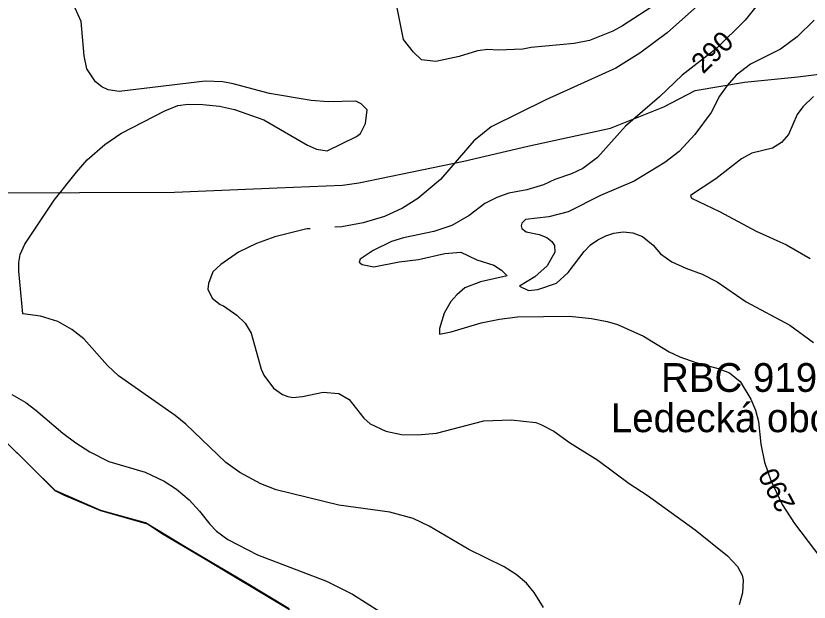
# Model space of a CAD drawing. Extents: x -662620 to -656370, y -1067090 to -1062990.
# Drawn here: x -662202 to -661678, y -1066558 to -1066171 of the extents above; entities that cross this region are included whole.
import ezdxf

# ---------------------------------------------------------------- set-up
doc = ezdxf.new("R2010")
doc.units = 0
for name, color, linetype in [('HRANICE_KATASTRÁLNÍHO_ÚZEMÍ', 7, 'Continuous'), ('Popis_-_Regionální_biocentrum_-_stávající', 7, 'Continuous'), ('Regionální_biocentrum_-_stávající', 7, 'Continuous'), ('VRSTEVNICE_ZDŮRAZNĚNÁ', 7, 'Continuous'), ('VRSTEVNICE_ZDŮRAZNĚNÁ_-_POPIS', 7, 'Continuous'), ('VRSTEVNICE_ZÁKLADNÍ', 7, 'Continuous')]:
    doc.layers.add(name, color=color, linetype=linetype)

msp = doc.modelspace()

# ---------------------------------------------------------------- linework, layer by layer
at = {"layer": 'HRANICE_KATASTRÁLNÍHO_ÚZEMÍ'}
msp.add_lwpolyline([(-662021.74, -1066563.07), (-662078.28, -1066529.15), (-662106.1, -1066512.72), (-662115.48, -1066506.62), (-662146.3, -1066497.76), (-662170.31, -1066487.67), (-662176.36, -1066484.43), (-662192.31, -1066468.76), (-662209.65, -1066451.51)], dxfattribs=at)
at = {"layer": 'Regionální_biocentrum_-_stávající'}
for points in [[(-662215.01, -1066287.86), (-662160.39, -1066287.51), (-662097.67, -1066287.27), (-662029.78, -1066284.52), (-661986.68, -1066282.77), (-661975.88, -1066281.2), (-661906.57, -1066266.8), (-661864.31, -1066256.88), (-661809.67, -1066245.03), (-661774.44, -1066231.02), (-661753.74, -1066220.18), (-661721.21, -1066214.63), (-661685.97, -1066211.19), (-661666.49, -1066208.88)], [(-662021.93, -1066562.42), (-662051.78, -1066544.4), (-662089.89, -1066522.03), (-662116.77, -1066505.74), (-662146.27, -1066497.59), (-662176.53, -1066484.26), (-662210.25, -1066450.85)]]:
    msp.add_lwpolyline(points, dxfattribs=at)
at = {"layer": 'VRSTEVNICE_ZDŮRAZNĚNÁ'}
for points in [[(-661709.26, -1066159.19), (-661720.68, -1066173.89), (-661739.66, -1066192.45), (-661762.21, -1066210.15), (-661777.2, -1066224.42), (-661799.75, -1066243.84), (-661818.31, -1066264.39), (-661827.87, -1066271.67), (-661835.3, -1066275.24), (-661846.43, -1066278.95), (-661853.85, -1066282.52), (-661864.98, -1066285.8), (-661876.69, -1066288.08), (-661884.68, -1066290.8), (-661892.68, -1066294.94), (-661902.95, -1066302.79), (-661914.37, -1066309.35), (-661926.36, -1066313.35), (-661946.35, -1066317.49), (-661954.34, -1066319.92), (-661966.33, -1066325.91), (-661975.04, -1066331.62), (-661975.61, -1066333.62), (-661973.75, -1066335.05), (-661966.04, -1066336.76), (-661949.2, -1066333.33), (-661936.35, -1066331.91), (-661918.94, -1066327.77), (-661908.38, -1066327.05), (-661897.82, -1066332.05)], [(-661897.82, -1066332.05), (-661886.68, -1066335.62), (-661881.69, -1066338.76), (-661877.87, -1066342.56), (-661895.53, -1066346.46), (-661905.81, -1066350.6), (-661911.09, -1066355.03), (-661915.09, -1066359.45), (-661919.51, -1066367.16), (-661922.51, -1066377.44), (-661922.51, -1066381.15), (-661914.94, -1066379.58), (-661894.96, -1066373.58), (-661882.97, -1066371.16), (-661870.98, -1066369.59), (-661836.72, -1066369.3), (-661822.16, -1066370.87), (-661811.89, -1066372.73), (-661805.04, -1066374.73), (-661787.91, -1066382.43), (-661770.78, -1066392.71), (-661763.93, -1066396.14), (-661753.36, -1066399.85), (-661738.52, -1066403.85), (-661731.1, -1066406.7), (-661723.96, -1066412.27), (-661716.97, -1066423.97), (-661713.83, -1066431.39), (-661711.97, -1066438.82), (-661710.26, -1066453.66), (-661707.83, -1066465.65), (-661703.69, -1066477.64), (-661696.27, -1066493.63), (-661688.13, -1066506.19), (-661657.44, -1066546.3)]]:
    msp.add_lwpolyline(points, dxfattribs=at)
at = {"layer": 'VRSTEVNICE_ZÁKLADNÍ'}
for points in [[(-661778.63, -1066162.47), (-661801.61, -1066177.61), (-661808.18, -1066181.17), (-661823.59, -1066187.31), (-661833.58, -1066189.31), (-661862.13, -1066191.74), (-661867.55, -1066192.88), (-661883.83, -1066193.59), (-661890.68, -1066193.16), (-661897.53, -1066194.02), (-661909.52, -1066197.73), (-661924.93, -1066201.01), (-661934.5, -1066200.02), (-661939.64, -1066194.88), (-661946.34, -1066186.6), (-661951.48, -1066161.19)], [(-661778.63, -1066162.47), (-661801.61, -1066177.61), (-661808.18, -1066181.17), (-661823.59, -1066187.31), (-661833.58, -1066189.31), (-661862.13, -1066191.74), (-661867.55, -1066192.88), (-661883.83, -1066193.59), (-661890.68, -1066193.16), (-661897.53, -1066194.02), (-661909.52, -1066197.73), (-661924.93, -1066201.01), (-661934.5, -1066200.02), (-661939.64, -1066194.88), (-661946.34, -1066186.6), (-661951.48, -1066161.19)], [(-662009.86, -1066256.4), (-662003.73, -1066258.97), (-661996.88, -1066259.97), (-661977.46, -1066250.69), (-661974.75, -1066248.69), (-661971.47, -1066242.12), (-661970.36, -1066232.9), (-661974.35, -1066229.11), (-661977.94, -1066227.17), (-661996.02, -1066227.71), (-662007.44, -1066226.85), (-662034.84, -1066222.28), (-662058.82, -1066215.86), (-662065.68, -1066214.57), (-662077.42, -1066213.97), (-662134.19, -1066221), (-662141.33, -1066219.86), (-662145.61, -1066217.71), (-662149.75, -1066214.57), (-662155.6, -1066205.87), (-662157.31, -1066197.3), (-662159.31, -1066174.75), (-662163.31, -1066165.9)], [(-662009.86, -1066256.4), (-662003.73, -1066258.97), (-661996.88, -1066259.97), (-661977.46, -1066250.69), (-661974.75, -1066248.69), (-661971.47, -1066242.12), (-661970.36, -1066232.9), (-661974.35, -1066229.11), (-661977.94, -1066227.17), (-661996.02, -1066227.71), (-662007.44, -1066226.85), (-662034.84, -1066222.28), (-662058.82, -1066215.86), (-662065.68, -1066214.57), (-662077.42, -1066213.97), (-662134.19, -1066221), (-662141.33, -1066219.86), (-662145.61, -1066217.71), (-662149.75, -1066214.57), (-662155.6, -1066205.87), (-662157.31, -1066197.3), (-662159.31, -1066174.75), (-662163.31, -1066165.9)], [(-661752.08, -1066164.33), (-661772.21, -1066182.17), (-661790.19, -1066195.59), (-661806.18, -1066205.44), (-661852.42, -1066226.42), (-661888.39, -1066244.26), (-661899.81, -1066253.4), (-661921.94, -1066278.95), (-661936.93, -1066291.51), (-661946.92, -1066297.93), (-661958.91, -1066303.36), (-661972.9, -1066307.64), (-661987.17, -1066310.21), (-661991.6, -1066310.48)], [(-661752.08, -1066164.33), (-661772.21, -1066182.17), (-661790.19, -1066195.59), (-661806.18, -1066205.44), (-661852.42, -1066226.42), (-661888.39, -1066244.26), (-661899.81, -1066253.4), (-661921.94, -1066278.95), (-661936.93, -1066291.51), (-661946.92, -1066297.93), (-661958.91, -1066303.36), (-661972.9, -1066307.64), (-661987.17, -1066310.21), (-661991.6, -1066310.48)], [(-661675.14, -1066173.75), (-661686.42, -1066184.89), (-661697.41, -1066192.88), (-661717.11, -1066202.87), (-661726.67, -1066210.01), (-661732.52, -1066216.86), (-661737.52, -1066224), (-661743.23, -1066234.7), (-661753.93, -1066249.26), (-661764.21, -1066260.54), (-661773.63, -1066267.82), (-661793.9, -1066280.09), (-661816.17, -1066289.51), (-661837.58, -1066300.36), (-661850.42, -1066303.64), (-661865.84, -1066305.36), (-661868.12, -1066307.93), (-661868.55, -1066309.5), (-661868.12, -1066311.35)], [(-661675.14, -1066173.75), (-661686.42, -1066184.89), (-661697.41, -1066192.88), (-661717.11, -1066202.87), (-661726.67, -1066210.01), (-661732.52, -1066216.86), (-661737.52, -1066224), (-661743.23, -1066234.7), (-661753.93, -1066249.26), (-661764.21, -1066260.54), (-661773.63, -1066267.82), (-661793.9, -1066280.09), (-661816.17, -1066289.51), (-661837.58, -1066300.36), (-661850.42, -1066303.64), (-661865.84, -1066305.36), (-661868.12, -1066307.93), (-661868.55, -1066309.5), (-661868.12, -1066311.35)], [(-661675.57, -1066224.14), (-661682.57, -1066231.13), (-661686.28, -1066236.13), (-661691.99, -1066249.26), (-661696.7, -1066254.54), (-661702.55, -1066258.25), (-661716.25, -1066261.68), (-661723.1, -1066265.25), (-661740.09, -1066278.66), (-661756.72, -1066289.45), (-661756.19, -1066291.37), (-661737.52, -1066300.08), (-661713.4, -1066313.21), (-661693.41, -1066322.06), (-661677.71, -1066331.05)], [(-661675.57, -1066224.14), (-661682.57, -1066231.13), (-661686.28, -1066236.13), (-661691.99, -1066249.26), (-661696.7, -1066254.54), (-661702.55, -1066258.25), (-661716.25, -1066261.68), (-661723.1, -1066265.25), (-661740.09, -1066278.66), (-661756.72, -1066289.45), (-661756.19, -1066291.37), (-661737.52, -1066300.08), (-661713.4, -1066313.21), (-661693.41, -1066322.06), (-661677.71, -1066331.05)], [(-661853.85, -1066561.57), (-661859.99, -1066551.58), (-661865.13, -1066545.58), (-661871.98, -1066539.73), (-661879.83, -1066534.74), (-661903.24, -1066523.32), (-661929.5, -1066507.76), (-661940.07, -1066502.76), (-661955.48, -1066498.62), (-661989.17, -1066493.91), (-662030.56, -1066483.92), (-662040.55, -1066479.93), (-662054.54, -1066472.36), (-662063.68, -1066465.79), (-662090.08, -1066440.53), (-662097.08, -1066434.82), (-662134.62, -1066408.7), (-662141.9, -1066401.85), (-662157.6, -1066384.29), (-662165.45, -1066378.01), (-662174.73, -1066372.73), (-662186.15, -1066369.3), (-662197.85, -1066367.73), (-662200.42, -1066339.47), (-662200.42, -1066333.76), (-662199.56, -1066328.62), (-662196.57, -1066321.77), (-662177.15, -1066292.65), (-662162.45, -1066274.1), (-662155.31, -1066266.1), (-662143.61, -1066255.83), (-662133.05, -1066248.55), (-662103.93, -1066233.56), (-662095.36, -1066230.13), (-662088.51, -1066229.28), (-662078.81, -1066229.42), (-662067.96, -1066230.56), (-662057.97, -1066232.7), (-662038.55, -1066239.7), (-662009.86, -1066256.4)], [(-661853.85, -1066561.57), (-661859.99, -1066551.58), (-661865.13, -1066545.58), (-661871.98, -1066539.73), (-661879.83, -1066534.74), (-661903.24, -1066523.32), (-661929.5, -1066507.76), (-661940.07, -1066502.76), (-661955.48, -1066498.62), (-661989.17, -1066493.91), (-662030.56, -1066483.92), (-662040.55, -1066479.93), (-662054.54, -1066472.36), (-662063.68, -1066465.79), (-662090.08, -1066440.53), (-662097.08, -1066434.82), (-662134.62, -1066408.7), (-662141.9, -1066401.85), (-662157.6, -1066384.29), (-662165.45, -1066378.01), (-662174.73, -1066372.73), (-662186.15, -1066369.3), (-662197.85, -1066367.73), (-662200.42, -1066339.47), (-662200.42, -1066333.76), (-662199.56, -1066328.62), (-662196.57, -1066321.77), (-662177.15, -1066292.65), (-662162.45, -1066274.1), (-662155.31, -1066266.1), (-662143.61, -1066255.83), (-662133.05, -1066248.55), (-662103.93, -1066233.56), (-662095.36, -1066230.13), (-662088.51, -1066229.28), (-662078.81, -1066229.42), (-662067.96, -1066230.56), (-662057.97, -1066232.7), (-662038.55, -1066239.7), (-662009.86, -1066256.4)], [(-662007.97, -1066311.49), (-662010.29, -1066311.64), (-662031.42, -1066316.78), (-662043.41, -1066321.2), (-662055.4, -1066327.05), (-662066.96, -1066335.19), (-662072.24, -1066339.9), (-662075.24, -1066347.61), (-662075.67, -1066351.46), (-662072.81, -1066357.31), (-662067.53, -1066361.59), (-662065.25, -1066362.45), (-662056.54, -1066368.59), (-662050.85, -1066373.91)], [(-662007.97, -1066311.49), (-662010.29, -1066311.64), (-662031.42, -1066316.78), (-662043.41, -1066321.2), (-662055.4, -1066327.05), (-662066.96, -1066335.19), (-662072.24, -1066339.9), (-662075.24, -1066347.61), (-662075.67, -1066351.46), (-662072.81, -1066357.31), (-662067.53, -1066361.59), (-662065.25, -1066362.45), (-662056.54, -1066368.59), (-662050.85, -1066373.91)], [(-661868.12, -1066311.35), (-661865.27, -1066313.49), (-661856.71, -1066315.21), (-661851.57, -1066317.2), (-661848.28, -1066319.92), (-661846.57, -1066322.63), (-661846.29, -1066327.05), (-661851.42, -1066336.05), (-661859.56, -1066343.32), (-661869.73, -1066349.39), (-661863.82, -1066352.24), (-661857.69, -1066351.71), (-661845.34, -1066347.49), (-661837.58, -1066340.47), (-661827.02, -1066326.48), (-661822.73, -1066322.2), (-661817.88, -1066318.77), (-661812.74, -1066316.2), (-661807.32, -1066314.49), (-661801.32, -1066313.63), (-661794.88, -1066314.12), (-661788.48, -1066316.63), (-661781.34, -1066322.34), (-661776.49, -1066328.05), (-661769.21, -1066333.33), (-661759.93, -1066337.61), (-661749.08, -1066341.47), (-661739.09, -1066346.46), (-661719.96, -1066359.74), (-661691.13, -1066375.15), (-661675.57, -1066386.57)], [(-661868.12, -1066311.35), (-661865.27, -1066313.49), (-661856.71, -1066315.21), (-661851.57, -1066317.2), (-661848.28, -1066319.92), (-661846.57, -1066322.63), (-661846.29, -1066327.05), (-661851.42, -1066336.05), (-661859.56, -1066343.32), (-661869.73, -1066349.39), (-661863.82, -1066352.24), (-661857.69, -1066351.71), (-661845.34, -1066347.49), (-661837.58, -1066340.47), (-661827.02, -1066326.48), (-661822.73, -1066322.2), (-661817.88, -1066318.77), (-661812.74, -1066316.2), (-661807.32, -1066314.49), (-661801.32, -1066313.63), (-661794.88, -1066314.12), (-661788.48, -1066316.63), (-661781.34, -1066322.34), (-661776.49, -1066328.05), (-661769.21, -1066333.33), (-661759.93, -1066337.61), (-661749.08, -1066341.47), (-661739.09, -1066346.46), (-661719.96, -1066359.74), (-661691.13, -1066375.15), (-661675.57, -1066386.57)], [(-662050.85, -1066373.91), (-662047.05, -1066380.46), (-662040.27, -1066404.27), (-662038.55, -1066408.27), (-662032.13, -1066416.83), (-662026.28, -1066420.83), (-662022.85, -1066422.26), (-662019.43, -1066422.83), (-662013.15, -1066422.26), (-661999.44, -1066419.4), (-661989.17, -1066420.26), (-661982.32, -1066424.26), (-661972.61, -1066436.53), (-661968.33, -1066440.39), (-661958.05, -1066445.24), (-661947.77, -1066447.24), (-661937.21, -1066447.52), (-661924.65, -1066446.38), (-661893.25, -1066438.39), (-661875.13, -1066437.58), (-661858.99, -1066439.53), (-661855.56, -1066440.67), (-661847, -1066445.1), (-661836.72, -1066452.52), (-661817.88, -1066464.37), (-661797.33, -1066479.64), (-661785.34, -1066487.49), (-661753.65, -1066510.33), (-661732.24, -1066527.46), (-661725.82, -1066534.45), (-661722.67, -1066540.16), (-661721.96, -1066543.59), (-661722.49, -1066551.8), (-661724.67, -1066559.86)], [(-662050.85, -1066373.91), (-662047.05, -1066380.46), (-662040.27, -1066404.27), (-662038.55, -1066408.27), (-662032.13, -1066416.83), (-662026.28, -1066420.83), (-662022.85, -1066422.26), (-662019.43, -1066422.83), (-662013.15, -1066422.26), (-661999.44, -1066419.4), (-661989.17, -1066420.26), (-661982.32, -1066424.26), (-661972.61, -1066436.53), (-661968.33, -1066440.39), (-661958.05, -1066445.24), (-661947.77, -1066447.24), (-661937.21, -1066447.52), (-661924.65, -1066446.38), (-661893.25, -1066438.39), (-661875.13, -1066437.58), (-661858.99, -1066439.53), (-661855.56, -1066440.67), (-661847, -1066445.1), (-661836.72, -1066452.52), (-661817.88, -1066464.37), (-661797.33, -1066479.64), (-661785.34, -1066487.49), (-661753.65, -1066510.33), (-661732.24, -1066527.46), (-661725.82, -1066534.45), (-661722.67, -1066540.16), (-661721.96, -1066543.59), (-661722.49, -1066551.8), (-661724.67, -1066559.86)], [(-662204.99, -1066420.97), (-662195.85, -1066426.26), (-662189.14, -1066431.25), (-662171.44, -1066446.38), (-662162.74, -1066452.95), (-662153.6, -1066458.8), (-662141.04, -1066465.22), (-662117.06, -1066472.22), (-662104.5, -1066478.07), (-662096.36, -1066483.49), (-662087.94, -1066490.49), (-662081.09, -1066497.91), (-662074.38, -1066506.62), (-662069.81, -1066511.18), (-662062.39, -1066516.61), (-662042.84, -1066526.74), (-661997.16, -1066544.16), (-661980.03, -1066552.72), (-661962.05, -1066564.14)], [(-662204.99, -1066420.97), (-662195.85, -1066426.26), (-662189.14, -1066431.25), (-662171.44, -1066446.38), (-662162.74, -1066452.95), (-662153.6, -1066458.8), (-662141.04, -1066465.22), (-662117.06, -1066472.22), (-662104.5, -1066478.07), (-662096.36, -1066483.49), (-662087.94, -1066490.49), (-662081.09, -1066497.91), (-662074.38, -1066506.62), (-662069.81, -1066511.18), (-662062.39, -1066516.61), (-662042.84, -1066526.74), (-661997.16, -1066544.16), (-661980.03, -1066552.72), (-661962.05, -1066564.14)]]:
    msp.add_lwpolyline(points, dxfattribs=at)

# ---------------------------------------------------------------- texts
at = {"layer": 'Popis_-_Regionální_biocentrum_-_stávající'}
for s, p in [('RBC 919', (-661776.23, -1066419.21)), ('Ledecká obora', (-661809.41, -1066445.81))]:
    msp.add_text(s, height=19, dxfattribs=at).set_placement(p)
at = {"layer": 'VRSTEVNICE_ZDŮRAZNĚNÁ_-_POPIS'}
for rotation, p in [(43.8302, (-661748.47, -1066209.74)), (118.211, (-661687.13, -1066493.93))]:
    msp.add_text('290', height=13.2, rotation=rotation, dxfattribs=at).set_placement(p)

doc.saveas('drawing.dxf')
